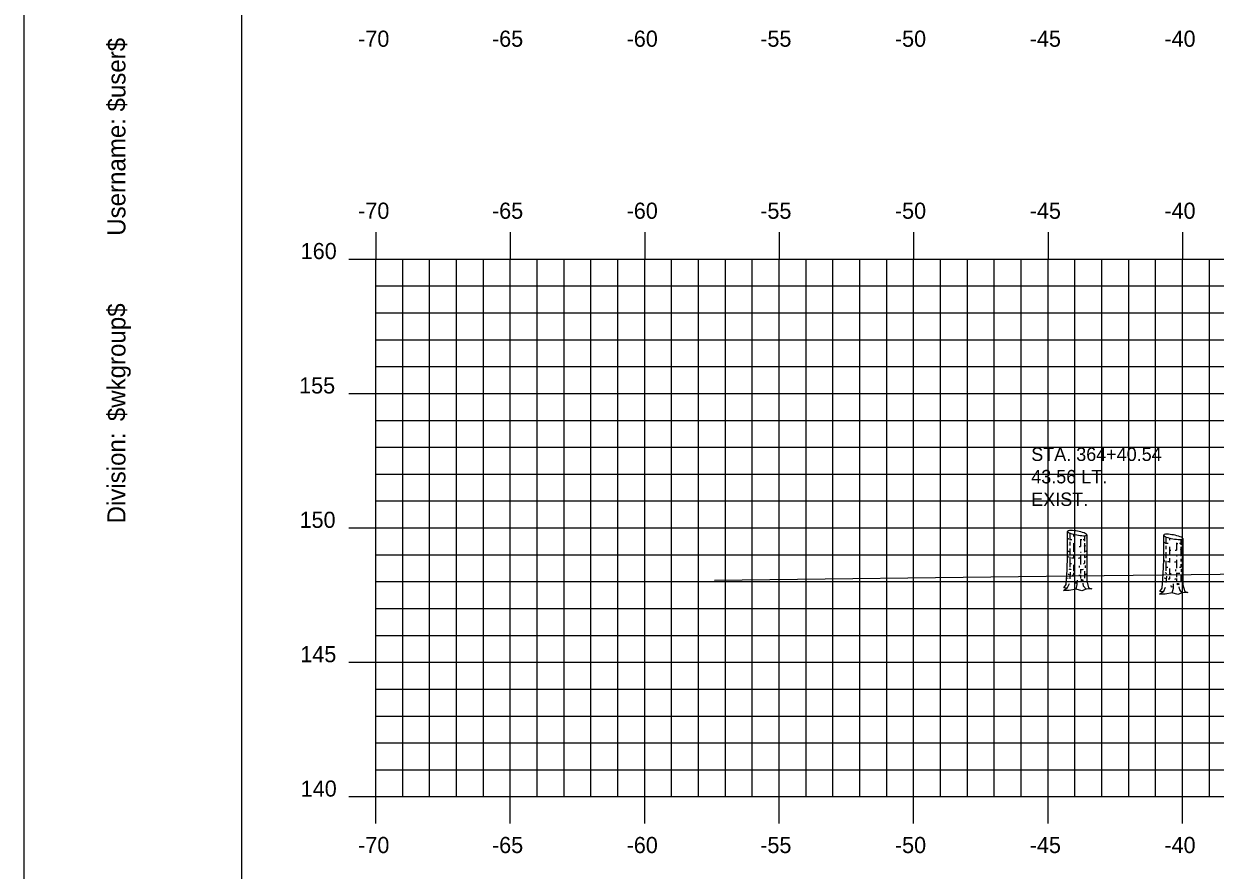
# Model space of a CAD drawing. Extents: x 1147190 to 1147360, y 608981 to 609091.
# Drawn here: x 1147189.85 to 1147234.16, y 609012.6 to 609044.09 of the extents above; entities that cross this region are included whole.
import ezdxf

# ---------------------------------------------------------------- set-up
doc = ezdxf.new("R2010")
doc.units = 0
for name, color, linetype in [('BORDER', 7, 'Continuous'), ('D_Text_Monospaced', 7, 'Continuous'), ('H_V ANNOTATION', 7, 'Continuous'), ('MAJOR', 7, 'Continuous'), ('MINOR', 7, 'Continuous'), ('PLOT BOUNDARY', 7, 'Continuous'), ('S_Roadway_Centerline', 7, 'Continuous'), ('S_Trees_Conifer_NonPay', 7, 'Continuous')]:
    doc.layers.add(name, color=color, linetype=linetype)

msp = doc.modelspace()

# ---------------------------------------------------------------- linework, layer by layer
at = {"layer": 'BORDER'}
msp.add_lwpolyline([(1147197.941, 608984.335), (1147357.941, 608984.335), (1147357.941, 609089.335), (1147197.941, 609089.335)], close=True, dxfattribs=at)
at = {"layer": 'MAJOR'}
for p, q in [((1147202.941, 609036.337), (1147202.941, 609035.335)), ((1147207.941, 609036.337), (1147207.941, 609035.335)), ((1147212.941, 609036.337), (1147212.941, 609035.335)), ((1147217.941, 609036.337), (1147217.941, 609035.335)), ((1147222.941, 609036.337), (1147222.941, 609035.335)), ((1147227.941, 609036.337), (1147227.941, 609035.335)), ((1147232.941, 609036.337), (1147232.941, 609035.335)), ((1147201.939, 609035.335), (1147202.941, 609035.335)), ((1147202.941, 609035.335), (1147342.941, 609035.335)), ((1147202.941, 609015.335), (1147202.941, 609035.335)), ((1147202.941, 609015.335), (1147202.941, 609035.335)), ((1147202.941, 609035.335), (1147342.941, 609035.335)), ((1147207.941, 609015.335), (1147207.941, 609035.335)), ((1147212.941, 609015.335), (1147212.941, 609035.335)), ((1147217.941, 609015.335), (1147217.941, 609035.335)), ((1147222.941, 609015.335), (1147222.941, 609035.335)), ((1147227.941, 609015.335), (1147227.941, 609035.335)), ((1147232.941, 609015.335), (1147232.941, 609035.335)), ((1147201.939, 609030.335), (1147202.941, 609030.335)), ((1147202.941, 609030.335), (1147342.941, 609030.335)), ((1147201.939, 609025.335), (1147202.941, 609025.335)), ((1147202.941, 609025.335), (1147342.941, 609025.335)), ((1147201.939, 609020.335), (1147202.941, 609020.335)), ((1147202.941, 609020.335), (1147342.941, 609020.335)), ((1147201.939, 609015.335), (1147202.941, 609015.335)), ((1147202.941, 609015.335), (1147342.941, 609015.335)), ((1147202.941, 609015.335), (1147342.941, 609015.335)), ((1147202.941, 609014.333), (1147202.941, 609015.335)), ((1147207.941, 609014.333), (1147207.941, 609015.335)), ((1147212.941, 609014.333), (1147212.941, 609015.335)), ((1147217.941, 609014.333), (1147217.941, 609015.335)), ((1147222.941, 609014.333), (1147222.941, 609015.335)), ((1147227.941, 609014.333), (1147227.941, 609015.335)), ((1147232.941, 609014.333), (1147232.941, 609015.335))]:
    msp.add_line(p, q, dxfattribs=at)
at = {"layer": 'MINOR'}
for p, q in [((1147203.941, 609015.335), (1147203.941, 609035.335)), ((1147204.941, 609015.335), (1147204.941, 609035.335)), ((1147205.941, 609015.335), (1147205.941, 609035.335)), ((1147206.941, 609015.335), (1147206.941, 609035.335)), ((1147208.941, 609015.335), (1147208.941, 609035.335)), ((1147209.941, 609015.335), (1147209.941, 609035.335)), ((1147210.941, 609015.335), (1147210.941, 609035.335)), ((1147211.941, 609015.335), (1147211.941, 609035.335)), ((1147213.941, 609015.335), (1147213.941, 609035.335)), ((1147214.941, 609015.335), (1147214.941, 609035.335)), ((1147215.941, 609015.335), (1147215.941, 609035.335)), ((1147216.941, 609015.335), (1147216.941, 609035.335)), ((1147218.941, 609015.335), (1147218.941, 609035.335)), ((1147219.941, 609015.335), (1147219.941, 609035.335)), ((1147220.941, 609015.335), (1147220.941, 609035.335)), ((1147221.941, 609015.335), (1147221.941, 609035.335)), ((1147223.941, 609015.335), (1147223.941, 609035.335)), ((1147224.941, 609015.335), (1147224.941, 609035.335)), ((1147225.941, 609015.335), (1147225.941, 609035.335)), ((1147226.941, 609015.335), (1147226.941, 609035.335)), ((1147228.941, 609015.335), (1147228.941, 609035.335)), ((1147229.941, 609015.335), (1147229.941, 609035.335)), ((1147230.941, 609015.335), (1147230.941, 609035.335)), ((1147231.941, 609015.335), (1147231.941, 609035.335)), ((1147233.941, 609015.335), (1147233.941, 609035.335)), ((1147202.941, 609034.335), (1147342.941, 609034.335)), ((1147202.941, 609034.335), (1147203.943, 609034.335)), ((1147202.941, 609033.335), (1147342.941, 609033.335)), ((1147202.941, 609033.335), (1147203.943, 609033.335)), ((1147202.941, 609032.335), (1147342.941, 609032.335)), ((1147202.941, 609032.335), (1147203.943, 609032.335)), ((1147202.941, 609031.335), (1147342.941, 609031.335)), ((1147202.941, 609031.335), (1147203.943, 609031.335)), ((1147202.941, 609029.335), (1147342.941, 609029.335)), ((1147202.941, 609029.335), (1147203.943, 609029.335)), ((1147202.941, 609028.335), (1147342.941, 609028.335)), ((1147202.941, 609028.335), (1147203.943, 609028.335)), ((1147202.941, 609027.335), (1147342.941, 609027.335)), ((1147202.941, 609027.335), (1147203.943, 609027.335)), ((1147202.941, 609026.335), (1147342.941, 609026.335)), ((1147202.941, 609026.335), (1147203.943, 609026.335)), ((1147202.941, 609024.335), (1147342.941, 609024.335)), ((1147202.941, 609024.335), (1147203.943, 609024.335)), ((1147202.941, 609023.335), (1147342.941, 609023.335)), ((1147202.941, 609023.335), (1147203.943, 609023.335)), ((1147202.941, 609022.335), (1147342.941, 609022.335)), ((1147202.941, 609022.335), (1147203.943, 609022.335)), ((1147202.941, 609021.335), (1147342.941, 609021.335)), ((1147202.941, 609021.335), (1147203.943, 609021.335)), ((1147202.941, 609019.335), (1147342.941, 609019.335)), ((1147202.941, 609019.335), (1147203.943, 609019.335)), ((1147202.941, 609018.335), (1147342.941, 609018.335)), ((1147202.941, 609018.335), (1147203.943, 609018.335)), ((1147202.941, 609017.335), (1147342.941, 609017.335)), ((1147202.941, 609017.335), (1147203.943, 609017.335)), ((1147202.941, 609016.335), (1147342.941, 609016.335)), ((1147202.941, 609016.335), (1147203.943, 609016.335))]:
    msp.add_line(p, q, dxfattribs=at)
at = {"layer": 'PLOT BOUNDARY'}
msp.add_lwpolyline([(1147189.848, 608981.276), (1147359.848, 608981.276), (1147359.848, 609091.276), (1147189.848, 609091.276)], close=True, dxfattribs=at)
at = {"layer": 'S_Roadway_Centerline'}
msp.add_lwpolyline([(1147215.532, 609023.394), (1147227.867, 609023.538), (1147246.188, 609023.744), (1147249.793, 609023.75), (1147254.992, 609023.718), (1147256.149, 609023.993), (1147258.083, 609024.547), (1147259.081, 609024.551), (1147260.862, 609024.571), (1147268.511, 609024.64), (1147272.288, 609024.696), (1147275.928, 609024.661), (1147283.359, 609024.561), (1147287.032, 609024.5), (1147287.423, 609024.486), (1147294.421, 609023.747), (1147295.199, 609023.66), (1147295.905, 609023.638), (1147300.455, 609023.669), (1147301.408, 609023.67), (1147307.138, 609023.764), (1147307.507, 609023.763), (1147312.134, 609023.662)], dxfattribs=at)
at = {"layer": 'S_Trees_Conifer_NonPay'}
for p, q in [((1147228.883, 609025.097), (1147228.883, 609025.019)), ((1147229.145, 609024.918), (1147229.145, 609024.644)), ((1147229.301, 609025.042), (1147229.301, 609024.837)), ((1147232.457, 609024.958), (1147232.457, 609024.879)), ((1147232.876, 609024.903), (1147232.876, 609024.698)), ((1147228.748, 609024.809), (1147228.748, 609024.678)), ((1147228.748, 609024.569), (1147228.748, 609024.343)), ((1147228.883, 609024.769), (1147228.883, 609024.444)), ((1147229.301, 609024.764), (1147229.301, 609024.433)), ((1147232.322, 609024.669), (1147232.322, 609024.539)), ((1147232.322, 609024.43), (1147232.322, 609024.204)), ((1147232.457, 609024.63), (1147232.457, 609024.305)), ((1147232.719, 609024.778), (1147232.719, 609024.505)), ((1147232.876, 609024.625), (1147232.876, 609024.293)), ((1147228.748, 609024.251), (1147228.748, 609023.875)), ((1147228.883, 609024.343), (1147228.883, 609024.189)), ((1147228.883, 609023.961), (1147228.883, 609023.727)), ((1147229.145, 609024.29), (1147229.145, 609023.972)), ((1147229.301, 609024.319), (1147229.301, 609024.24)), ((1147229.301, 609024.126), (1147229.301, 609024.016)), ((1147229.318, 609023.939), (1147229.318, 609023.842)), ((1147232.322, 609024.112), (1147232.322, 609023.736)), ((1147232.457, 609024.204), (1147232.457, 609024.05)), ((1147232.719, 609024.151), (1147232.719, 609023.833)), ((1147232.876, 609024.179), (1147232.876, 609024.101)), ((1147232.876, 609023.986), (1147232.876, 609023.877)), ((1147228.767, 609023.682), (1147228.75, 609023.437)), ((1147228.883, 609023.665), (1147228.883, 609023.579)), ((1147229.103, 609023.927), (1147229.103, 609023.858)), ((1147229.145, 609023.802), (1147229.145, 609023.643)), ((1147229.145, 609023.585), (1147229.145, 609023.454)), ((1147229.301, 609023.727), (1147229.301, 609023.46)), ((1147232.341, 609023.543), (1147232.324, 609023.297)), ((1147232.457, 609023.822), (1147232.457, 609023.588)), ((1147232.457, 609023.526), (1147232.457, 609023.44)), ((1147232.677, 609023.788), (1147232.677, 609023.719)), ((1147232.719, 609023.663), (1147232.719, 609023.503)), ((1147232.876, 609023.588), (1147232.876, 609023.32)), ((1147232.893, 609023.799), (1147232.893, 609023.702)), ((1147228.688, 609023.454), (1147228.628, 609023.46)), ((1147232.262, 609023.314), (1147232.202, 609023.321)), ((1147232.719, 609023.446), (1147232.719, 609023.314))]:
    msp.add_line(p, q, dxfattribs=at)
for points in [[(1147229.38, 609025.076), (1147229.38, 609023.359), (1147229.45, 609023.102), (1147229.569, 609023.068), (1147229.353, 609023.051), (1147229.193, 609022.993), (1147228.984, 609023.051), (1147228.721, 609023.004), (1147228.515, 609023.01), (1147228.667, 609023.113), (1147228.738, 609023.267)], [(1147228.637, 609023.093), (1147228.521, 609023.102), (1147228.613, 609023.227), (1147228.647, 609023.768), (1147228.667, 609024.285), (1147228.667, 609025.204)], [(1147228.748, 609025.138), (1147228.748, 609025.041), (1147228.748, 609024.876)], [(1147232.954, 609024.937), (1147232.954, 609023.219), (1147233.024, 609022.963), (1147233.143, 609022.929), (1147232.927, 609022.912), (1147232.767, 609022.854), (1147232.558, 609022.912), (1147232.296, 609022.865), (1147232.089, 609022.871), (1147232.241, 609022.974), (1147232.313, 609023.127)], [(1147232.212, 609022.954), (1147232.095, 609022.963), (1147232.187, 609023.088), (1147232.221, 609023.629), (1147232.241, 609024.146), (1147232.241, 609025.065)], [(1147232.322, 609024.999), (1147232.322, 609024.902), (1147232.322, 609024.737)], [(1147229.03, 609023.277), (1147228.961, 609023.272), (1147228.943, 609023.324)], [(1147228.984, 609023.051), (1147229.028, 609023.227), (1147229.034, 609023.392)], [(1147229.221, 609023.414), (1147229.233, 609023.37), (1147229.182, 609023.359), (1147229.182, 609023.42)], [(1147229.353, 609023.051), (1147229.263, 609023.164), (1147229.246, 609023.278)], [(1147232.605, 609023.138), (1147232.535, 609023.133), (1147232.517, 609023.185)], [(1147232.558, 609022.912), (1147232.603, 609023.088), (1147232.608, 609023.253)], [(1147232.796, 609023.275), (1147232.807, 609023.23), (1147232.756, 609023.219), (1147232.756, 609023.281)], [(1147232.927, 609022.912), (1147232.837, 609023.024), (1147232.82, 609023.139)]]:
    msp.add_lwpolyline(points, dxfattribs=at)
for centre, radius, start, end in [((1147228.681, 609025.202), 0.0141, 153.567, 169.6202), ((1147228.681, 609025.202), 0.0141, 169.6202, 185.6733), ((1147228.686, 609025.202), 0.0186, 185.6733, 199.6202), ((1147228.685, 609024.962), 0.0189, 196.0515, 210), ((1147228.693, 609025.205), 0.0263, 199.6202, 218.3805), ((1147228.685, 609025.2), 0.0186, 139.6202, 153.567), ((1147228.692, 609024.966), 0.0267, 210, 228.7494), ((1147228.691, 609025.195), 0.0263, 120.8598, 139.6202), ((1147228.729, 609025.234), 0.0729, 218.3805, 229.6202), ((1147228.723, 609025.001), 0.0738, 228.7494, 240), ((1147228.715, 609025.155), 0.0729, 109.6202, 120.8598), ((1147228.841, 609025.365), 0.245, 229.6202, 251.6054), ((1147228.808, 609025.149), 0.245, 240, 248.2347), ((1147228.773, 609024.993), 0.245, 87.6349, 109.6202), ((1147228.808, 609025.149), 0.245, 255.8141, 261.8968), ((1147229.34, 609026.865), 1.825, 251.6054, 259.6202), ((1147229.023, 609026.657), 1.767, 261.8968, 263.7551), ((1147228.708, 609023.414), 1.825, 79.6202, 87.6349), ((1147229.34, 609026.865), 1.825, 259.6202, 267.6349), ((1147228.708, 609023.414), 1.825, 71.6054, 79.6202), ((1147229.023, 609026.657), 1.767, 273.9501, 275.6733), ((1147229.023, 609026.657), 1.767, 277.395, 278.1032), ((1147229.275, 609025.286), 0.245, 267.6349, 289.6202), ((1147229.238, 609025.149), 0.245, 278.1032, 285.1539), ((1147229.206, 609024.913), 0.245, 49.6202, 71.6054), ((1147229.332, 609025.124), 0.0729, 289.6202, 300.8598), ((1147229.318, 609025.045), 0.0729, 38.3805, 49.6202), ((1147229.356, 609025.084), 0.0263, 300.8598, 319.6202), ((1147229.354, 609025.074), 0.0263, 19.6202, 38.3805), ((1147229.362, 609025.079), 0.0186, 319.6202, 333.567), ((1147229.362, 609025.076), 0.0186, 5.6733, 19.6202), ((1147229.366, 609025.077), 0.0141, 333.567, 349.6202), ((1147229.365, 609024.961), 0.0143, 343.9485, 360), ((1147229.366, 609025.077), 0.0141, 349.6202, 5.6733), ((1147232.255, 609025.063), 0.0141, 153.567, 169.6202), ((1147232.255, 609025.063), 0.0141, 169.6202, 185.6733), ((1147232.26, 609025.063), 0.0186, 185.6733, 199.6202), ((1147232.259, 609024.823), 0.0189, 196.0515, 210), ((1147232.267, 609025.066), 0.0263, 199.6202, 218.3805), ((1147232.259, 609025.061), 0.0186, 139.6202, 153.567), ((1147232.265, 609025.056), 0.0263, 120.8598, 139.6202), ((1147232.304, 609025.095), 0.0729, 218.3805, 229.6202), ((1147232.289, 609025.016), 0.0729, 109.6202, 120.8598), ((1147232.415, 609025.226), 0.245, 229.6202, 251.6054), ((1147232.347, 609024.853), 0.245, 87.6349, 109.6202), ((1147232.914, 609026.725), 1.825, 251.6054, 259.6202), ((1147232.282, 609023.275), 1.825, 79.6202, 87.6349), ((1147232.914, 609026.725), 1.825, 259.6202, 267.6349), ((1147232.282, 609023.275), 1.825, 71.6054, 79.6202), ((1147232.849, 609025.147), 0.245, 267.6349, 289.6202), ((1147232.78, 609024.774), 0.245, 49.6202, 71.6054), ((1147232.906, 609024.984), 0.0729, 289.6202, 300.8598), ((1147232.892, 609024.905), 0.0729, 38.3805, 49.6202), ((1147232.93, 609024.944), 0.0263, 300.8598, 319.6202), ((1147232.929, 609024.934), 0.0263, 19.6202, 38.3805), ((1147232.936, 609024.939), 0.0186, 319.6202, 333.567), ((1147232.936, 609024.937), 0.0186, 5.6733, 19.6202), ((1147232.94, 609024.937), 0.0141, 333.567, 349.6202), ((1147232.94, 609024.821), 0.0143, 343.9485, 360), ((1147232.94, 609024.937), 0.0141, 349.6202, 5.6733), ((1147228.683, 609024.71), 0.0189, 196.0515, 210), ((1147228.69, 609024.714), 0.0267, 210, 228.7494), ((1147228.685, 609024.496), 0.0189, 196.0515, 210), ((1147228.692, 609024.5), 0.0267, 210, 228.7494), ((1147228.723, 609024.535), 0.0738, 228.7494, 240), ((1147228.808, 609024.683), 0.245, 240, 255.8141), ((1147229.021, 609026.405), 1.767, 265.5153, 267.2779), ((1147229.021, 609026.405), 1.767, 272.4038, 274.1009), ((1147229.023, 609026.191), 1.767, 273.8675, 274.7715), ((1147229.236, 609024.897), 0.245, 282.4625, 295.6852), ((1147229.238, 609024.683), 0.245, 282.4546, 285.1539), ((1147229.238, 609024.683), 0.245, 293.2086, 300), ((1147229.323, 609024.535), 0.0738, 300, 311.2506), ((1147229.354, 609024.5), 0.0267, 311.2506, 330), ((1147229.361, 609024.496), 0.0189, 330, 343.9485), ((1147229.365, 609024.495), 0.0143, 343.9485, 360), ((1147232.258, 609024.571), 0.0189, 196.0515, 210), ((1147232.264, 609024.574), 0.0267, 210, 228.7494), ((1147232.266, 609024.827), 0.0267, 210, 228.7494), ((1147232.297, 609024.862), 0.0738, 228.7494, 240), ((1147232.383, 609025.01), 0.245, 240, 248.2347), ((1147232.383, 609025.01), 0.245, 255.8141, 261.8968), ((1147232.597, 609026.517), 1.767, 261.8968, 263.7551), ((1147232.595, 609026.265), 1.767, 265.5153, 267.2779), ((1147232.595, 609026.265), 1.767, 272.4038, 274.1009), ((1147232.597, 609026.517), 1.767, 273.9501, 275.6733), ((1147232.597, 609026.517), 1.767, 277.395, 278.1032), ((1147232.812, 609025.01), 0.245, 278.1032, 285.1539), ((1147232.81, 609024.758), 0.245, 282.4625, 295.6852), ((1147228.685, 609024.285), 0.0189, 196.0515, 210), ((1147228.692, 609024.289), 0.0267, 210, 228.7494), ((1147228.723, 609024.324), 0.0738, 228.7494, 240), ((1147228.808, 609024.472), 0.245, 240, 247.8076), ((1147228.809, 609024.252), 0.245, 255.6793, 261.8968), ((1147229.024, 609025.76), 1.767, 261.8968, 263.2034), ((1147229.023, 609025.979), 1.767, 262.9974, 265.4639), ((1147229.023, 609025.979), 1.767, 271.4475, 273.9571), ((1147229.024, 609025.76), 1.767, 277.55, 278.1032), ((1147229.238, 609024.252), 0.245, 278.1032, 285.0186), ((1147229.238, 609024.472), 0.245, 285.0486, 300), ((1147229.323, 609024.324), 0.0738, 300, 311.2506), ((1147229.354, 609024.289), 0.0267, 311.2506, 330), ((1147229.361, 609024.285), 0.0189, 330, 343.9485), ((1147229.365, 609024.283), 0.0143, 343.9485, 360), ((1147232.259, 609024.357), 0.0189, 196.0515, 210), ((1147232.259, 609024.145), 0.0189, 196.0515, 210), ((1147232.266, 609024.361), 0.0267, 210, 228.7494), ((1147232.266, 609024.149), 0.0267, 210, 228.7494), ((1147232.297, 609024.185), 0.0738, 228.7494, 240), ((1147232.297, 609024.396), 0.0738, 228.7494, 240), ((1147232.383, 609024.544), 0.245, 240, 255.8141), ((1147232.382, 609024.333), 0.245, 240, 247.8076), ((1147232.597, 609025.84), 1.767, 262.9974, 265.4639), ((1147232.597, 609025.84), 1.767, 271.4475, 273.9571), ((1147232.597, 609026.051), 1.767, 273.8675, 274.7715), ((1147232.812, 609024.544), 0.245, 282.4546, 285.1539), ((1147232.812, 609024.333), 0.245, 285.0486, 300), ((1147232.812, 609024.544), 0.245, 293.2086, 300), ((1147232.897, 609024.396), 0.0738, 300, 311.2506), ((1147232.897, 609024.185), 0.0738, 300, 311.2506), ((1147232.928, 609024.361), 0.0267, 311.2506, 330), ((1147232.928, 609024.149), 0.0267, 311.2506, 330), ((1147232.935, 609024.357), 0.0189, 330, 343.9485), ((1147232.935, 609024.145), 0.0189, 330, 343.9485), ((1147232.94, 609024.355), 0.0143, 343.9485, 360), ((1147232.939, 609024.144), 0.0143, 343.9485, 360), ((1147228.724, 609023.682), 0.0738, 237.95, 240), ((1147228.81, 609023.83), 0.245, 240, 255.9316), ((1147228.809, 609024.035), 0.245, 245.3944, 261.8968), ((1147229.024, 609025.543), 1.767, 261.8968, 262.37), ((1147229.024, 609025.337), 1.767, 263.6994, 265.7224), ((1147229.024, 609025.543), 1.767, 265.4388, 267.3707), ((1147229.024, 609025.337), 1.767, 271.7813, 273.9138), ((1147229.024, 609025.543), 1.767, 274.9504, 277.7378), ((1147229.239, 609023.83), 0.245, 290.8325, 300), ((1147229.324, 609023.682), 0.0738, 300, 311.2506), ((1147229.355, 609023.646), 0.0267, 311.2506, 330), ((1147229.362, 609023.642), 0.0189, 330, 343.9485), ((1147229.366, 609023.847), 0.0143, 343.9485, 360), ((1147229.367, 609023.641), 0.0143, 343.9485, 360), ((1147232.383, 609023.896), 0.245, 245.3944, 261.8968), ((1147232.383, 609024.113), 0.245, 255.6793, 261.8968), ((1147232.598, 609025.621), 1.767, 261.8968, 263.2034), ((1147232.598, 609025.404), 1.767, 261.8968, 262.37), ((1147232.598, 609025.404), 1.767, 265.4388, 267.3707), ((1147232.598, 609025.404), 1.767, 274.9504, 277.7378), ((1147232.598, 609025.621), 1.767, 277.55, 278.1032), ((1147232.812, 609024.113), 0.245, 278.1032, 285.0186), ((1147232.898, 609023.542), 0.0738, 300, 311.2506), ((1147232.929, 609023.507), 0.0267, 311.2506, 330), ((1147232.936, 609023.503), 0.0189, 330, 343.9485), ((1147232.94, 609023.708), 0.0143, 343.9485, 360), ((1147232.941, 609023.502), 0.0143, 343.9485, 360), ((1147232.298, 609023.542), 0.0738, 237.95, 240), ((1147232.384, 609023.69), 0.245, 240, 255.9316), ((1147232.598, 609025.198), 1.767, 263.6994, 265.7224), ((1147232.598, 609025.198), 1.767, 271.7813, 273.9138), ((1147232.813, 609023.69), 0.245, 290.8325, 300)]:
    msp.add_arc(centre, radius, start, end, dxfattribs=at)

# ---------------------------------------------------------------- texts
at = {"layer": 'BORDER'}
for s, p in [('$user$', (1147193.626, 609040.827)), ('Username:', (1147193.626, 609036.203)), ('$wkgroup$', (1147193.626, 609029.305)), ('Division:', (1147193.626, 609025.501))]:
    msp.add_text(s, height=0.6696, rotation=90, dxfattribs=at).set_placement(p)
at = {"layer": 'D_Text_Monospaced'}
for s, height, p in [('STA. 364+40.54', 0.49998, (1147227.316, 609027.824)), ('43.56 LT.', 0.5, (1147227.316, 609026.99)), ('EXIST. ', 0.5, (1147227.316, 609026.15))]:
    msp.add_text(s, height=height, dxfattribs=at).set_placement(p)
at = {"layer": 'H_V ANNOTATION'}
for s, p in [('-70', (1147202.282, 609043.235)), ('-65', (1147207.259, 609043.235)), ('-60', (1147212.267, 609043.235)), ('-55', (1147217.237, 609043.235)), ('-50', (1147222.245, 609043.235)), ('-45', (1147227.259, 609043.235)), ('-40', (1147232.267, 609043.235)), ('-70', (1147202.282, 609036.835)), ('-65', (1147207.259, 609036.835)), ('-60', (1147212.267, 609036.835)), ('-55', (1147217.237, 609036.835)), ('-50', (1147222.245, 609036.835)), ('-45', (1147227.259, 609036.835)), ('-40', (1147232.267, 609036.835)), ('160', (1147200.146, 609035.335)), ('155', (1147200.087, 609030.335)), ('150', (1147200.103, 609025.335)), ('145', (1147200.13, 609020.335)), ('140', (1147200.146, 609015.335)), ('-70', (1147202.282, 609013.235)), ('-65', (1147207.259, 609013.235)), ('-60', (1147212.267, 609013.235)), ('-55', (1147217.237, 609013.235)), ('-50', (1147222.245, 609013.235)), ('-45', (1147227.259, 609013.235)), ('-40', (1147232.267, 609013.235))]:
    msp.add_text(s, height=0.6, dxfattribs=at).set_placement(p)
at = {"layer": 'MAJOR'}
msp.add_text('-', height=0.006, dxfattribs=at).set_placement((1147202.936, 609015.335))

doc.saveas('drawing.dxf')
